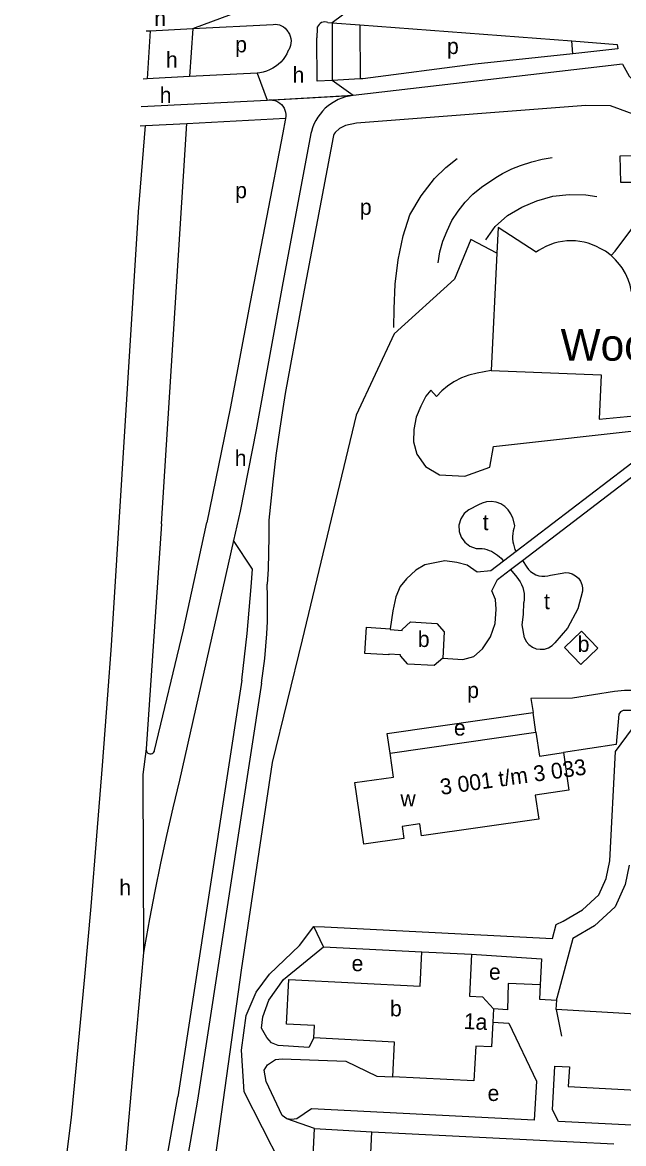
# Model space of a CAD drawing. Extents: x 161773 to 163836, y 384796 to 386521.
# Drawn here: x 161829.4 to 161981.1, y 385102.4 to 385385.3 of the extents above; entities that cross this region are included whole.
import ezdxf

# ---------------------------------------------------------------- set-up
doc = ezdxf.new("R2010")
doc.units = 0
for name, color, linetype in [('BLT_Basislijn', 7, 'Continuous'), ('BLT_Bebouwing', 7, 'Continuous'), ('BLT_Bebouwing_beschrifting', 7, 'Continuous'), ('BLT_Centroide', 7, 'Continuous'), ('BLT_Huisnummer', 7, 'Continuous'), ('BLT_Huisnummer_reeks', 7, 'Continuous'), ('BLT_Vlakafsluiter', 7, 'Continuous')]:
    doc.layers.add(name, color=color, linetype=linetype)

msp = doc.modelspace()

# ---------------------------------------------------------------- linework, layer by layer
at = {"layer": 'BLT_Basislijn'}
for p, q in [((161861.61, 385383.24), (161872.38, 385383.79)), ((161872.38, 385383.79), (161871.51, 385371.65)), ((161872.38, 385383.79), (161892.67, 385384.82)), ((161903.73, 385383.9), (161903.66, 385381.41)), ((161906.48, 385385.3), (161907.55, 385385.22)), ((161907.55, 385385.22), (161907.55, 385370.71)), ((161907.55, 385385.22), (161914.56, 385384.69)), ((161914.56, 385384.69), (161914.63, 385371.07)), ((161860.62, 385383.19), (161861.61, 385383.24)), ((161861.61, 385383.24), (161860.87, 385371.1)), ((161968.27, 385377.44), (161968.05, 385380.64)), ((161979.51, 385379.77), (161979.65, 385378.66)), ((161888.63, 385372.54), (161871.51, 385371.65)), ((161975.8, 385374.19), (161912.89, 385366.87)), ((161980.8, 385374.77), (161975.8, 385374.19)), ((161860.87, 385371.1), (161859.83, 385371.04)), ((161871.51, 385371.65), (161860.87, 385371.1)), ((161914.63, 385371.07), (161907.55, 385370.71)), ((161859.38, 385364.1), (161891.12, 385365.7)), ((161971.57, 385364.37), (161913.7, 385359.92)), ((161870.84, 385359.86), (161895.81, 385361.17)), ((161858.63, 385337.56), (161860.4, 385359.32)), ((161859.06, 385359.24), (161860.4, 385359.32)), ((161860.4, 385359.32), (161870.84, 385359.86)), ((161864.48, 385258.81), (161870.84, 385359.86)), ((161895.68, 385360.64), (161895.07, 385357.44)), ((161895.07, 385357.44), (161886.84, 385314.74)), ((161902.2, 385357.34), (161894.91, 385318.73)), ((161907.79, 385356.41), (161900.5, 385317.8)), ((161851.84, 385228.1), (161858.63, 385337.56)), ((161895.12, 385287.9), (161894.38, 385282.93)), ((161884.31, 385262.02), (161882.64, 385254.61)), ((161944.45, 385263.58), (161942.07, 385262.37)), ((161953.06, 385260.39), (161953.57, 385258.28)), ((161864.48, 385258.81), (161860.59, 385202.02)), ((161882.64, 385254.61), (161869, 385194.13)), ((161887.42, 385247.34), (161882.64, 385254.61)), ((161953.67, 385252.37), (161954.02, 385251.85)), ((161950.21, 385250.11), (161950.8, 385249.39)), ((161955.56, 385249.56), (161956.7, 385247.87)), ((161952.57, 385247.27), (161954.14, 385245.37)), ((161962.62, 385245.85), (161965.64, 385246.4)), ((161970.77, 385241.85), (161969.54, 385237.33)), ((161955.8, 385235.92), (161955.92, 385238.97)), ((161969.54, 385237.33), (161966.98, 385232.47)), ((161955.48, 385233.36), (161955.8, 385235.92)), ((161956.06, 385230.04), (161955.48, 385233.36)), ((161966.98, 385232.47), (161963.77, 385228.79)), ((161884.74, 385219.35), (161868.6, 385114.18)), ((161889.68, 385218.59), (161873.54, 385113.42)), ((161958.98, 385206.27), (161958.27, 385211.22)), ((161905.36, 385152.08), (161902.89, 385157.22)), ((161905.36, 385152.08), (161930.21, 385150.85)), ((161859.89, 385150.65), (161857.58, 385124.36)), ((161964.1, 385136.25), (161964.24, 385138.65)), ((161964.24, 385138.65), (161964.27, 385139.11)), ((161964.1, 385136.25), (161965.45, 385129.52)), ((161873.54, 385113.42), (161848.95, 384970.34)), ((161903.08, 385106.19), (161896.1, 385108.63)), ((161903.08, 385106.19), (161917.59, 385105.41))]:
    msp.add_line(p, q, dxfattribs=at)
for points in [[(161892.67, 385384.82), (161893.21, 385384.86), (161893.76, 385384.81), (161894.29, 385384.69), (161894.79, 385384.49), (161895.26, 385384.22), (161895.69, 385383.88), (161896.06, 385383.49), (161896.37, 385383.04), (161896.46, 385382.87)], [(161906.48, 385385.3), (161906.09, 385385.41), (161905.68, 385385.45), (161905.28, 385385.4), (161904.89, 385385.27), (161904.54, 385385.08), (161904.23, 385384.81), (161903.98, 385384.49), (161903.8, 385384.13), (161903.73, 385383.9)], [(161914.56, 385384.69), (161968.05, 385380.64)], [(161896.46, 385382.87), (161896.75, 385382.36), (161896.96, 385381.82), (161897.1, 385381.25), (161897.16, 385380.67), (161897.13, 385380.09), (161897.03, 385379.51), (161896.85, 385378.96), (161896.6, 385378.43), (161896.46, 385378.21)], [(161907.55, 385370.71), (161903.75, 385370.52), (161903.66, 385381.41)], [(161896.46, 385378.21), (161896.09, 385377.43), (161895.65, 385376.69), (161895.14, 385375.99), (161894.57, 385375.34), (161893.94, 385374.75), (161893.26, 385374.22), (161892.54, 385373.75), (161891.77, 385373.36), (161890.97, 385373.03), (161890.14, 385372.79), (161889.3, 385372.62), (161888.63, 385372.54)], [(161968.05, 385380.64), (161979.51, 385379.77)], [(161979.65, 385378.66), (161968.27, 385377.44)], [(161968.27, 385377.44), (161943.61, 385374.79), (161915.32, 385371.1), (161914.63, 385371.07)], [(161980.8, 385374.77), (161982.52, 385371.79), (161984.92, 385369.15), (161987.89, 385367.09), (161991.2, 385365.76), (161994.59, 385365.19), (161998.03, 385365.37), (162001.47, 385366.31), (162004.66, 385368.02), (162007.35, 385370.37), (162009.39, 385373.14)], [(161912.32, 385366.79), (161911.91, 385366.73), (161910.95, 385366.51), (161910.01, 385366.21), (161909.09, 385365.84), (161908.21, 385365.4), (161907.36, 385364.88), (161906.56, 385364.3), (161905.81, 385363.66), (161905.12, 385362.96), (161904.48, 385362.2), (161903.9, 385361.4), (161903.4, 385360.55), (161902.96, 385359.66), (161902.6, 385358.74), (161902.31, 385357.79), (161902.2, 385357.34)], [(161912.89, 385366.87), (161912.32, 385366.79)], [(161891.12, 385365.7), (161891.67, 385365.78), (161892.23, 385365.77), (161892.51, 385365.73)], [(161892.51, 385365.73), (161892.75, 385365.7)], [(161892.75, 385365.7), (161892.79, 385365.69), (161893.33, 385365.53), (161893.84, 385365.29), (161894.31, 385364.99), (161894.73, 385364.62), (161895.1, 385364.19), (161895.4, 385363.72), (161895.63, 385363.21), (161895.78, 385362.67), (161895.86, 385362.11), (161895.86, 385361.55), (161895.81, 385361.17)], [(162016.9, 385359.59), (162013.18, 385360.83), (162006.47, 385360.83), (161998.06, 385359.53), (161988.57, 385360.3), (161977.78, 385364.28), (161971.57, 385364.37)], [(161895.81, 385361.17), (161895.78, 385361), (161895.68, 385360.64)], [(161913.7, 385359.92), (161910.91, 385359.33), (161909.37, 385358.52), (161908.27, 385357.55), (161908.03, 385357.18), (161907.87, 385356.77), (161907.79, 385356.41)], [(161923.15, 385308.35), (161923.22, 385313.09), (161923.46, 385319.28), (161924.22, 385325.43), (161925.47, 385331.5), (161927.15, 385336.79), (161930.02, 385341.55), (161933.39, 385345.96), (161936.26, 385348.68), (161939.12, 385351.03)], [(161934.3, 385324.63), (161934.72, 385327.44), (161935.48, 385330.17), (161936.59, 385332.78), (161937.79, 385335.35), (161939.33, 385337.73), (161941.11, 385339.94), (161943.08, 385341.98), (161945.28, 385343.77), (161947.05, 385344.99), (161949.28, 385346.44), (161950.58, 385347.18), (161952.93, 385348.35), (161955.09, 385349.24), (161957.91, 385350.19), (161960.54, 385350.84), (161963.08, 385351.28)], [(161977.93, 385326.48), (161978.99, 385327.63), (161982.97, 385332.91), (161984.29, 385334.93), (161984.67, 385336.09), (161984.76, 385337.27), (161985, 385339.88), (161985.51, 385342.13), (161986.57, 385344.92), (161980.39, 385344.97), (161980.27, 385351.7), (161993.54, 385351.93), (161993.59, 385349.34), (162056.8, 385350.57)], [(161946.32, 385330.44), (161948.66, 385333.86), (161951.83, 385336.57), (161955.39, 385338.74), (161959.23, 385340.35), (161963.24, 385341.47), (161967.39, 385341.91), (161971.55, 385341.84), (161974.36, 385341.42)], [(161949.14, 385327.14), (161942.55, 385330.53), (161938.43, 385320.55), (161923.2, 385306.75), (161913.58, 385286.21), (161900, 385229.51), (161892.42, 385198.57), (161884.59, 385146.22), (161864.49, 385001.44)], [(161894.91, 385318.73), (161888.4, 385282.54), (161884.31, 385262.02)], [(161900.5, 385317.8), (161895.69, 385291.68), (161895.12, 385287.9)], [(161886.84, 385314.74), (161881.79, 385287.89), (161875.95, 385259.11)], [(161947.71, 385297.47), (161944.11, 385296.86), (161942.08, 385296.31), (161940.2, 385295.63), (161938.28, 385294.61), (161936.65, 385293.57), (161935.21, 385292.37), (161933.92, 385290.94), (161932.42, 385292.55), (161931.22, 385290.98), (161929.89, 385288.52), (161928.74, 385285.68), (161928.15, 385282.64), (161928.1, 385279.52), (161928.91, 385276.37), (161931.07, 385273.27), (161934.62, 385271.18), (161941.04, 385270.85), (161947.37, 385273.09), (161948.31, 385278.29), (161988.32, 385282.74)], [(161894.38, 385282.93), (161893.35, 385276.03), (161892.58, 385269.41), (161891.6, 385259.69)], [(161986.38, 385276.59), (161954.02, 385251.85)], [(161955.56, 385249.56), (161988.48, 385274.72), (161990.14, 385273.9), (161992.17, 385273.83), (161994.24, 385274.37), (161996.15, 385274.27)], [(161942.07, 385262.37), (161940.88, 385261.39), (161939.99, 385260.03), (161939.55, 385258.45), (161939.6, 385256.86), (161940.09, 385255.43), (161941.01, 385254.14), (161942.33, 385253.15), (161943.86, 385252.62), (161945.4, 385252.56)], [(161953.06, 385260.39), (161952.64, 385261.36), (161952.01, 385262.31), (161951.15, 385263.15), (161950.1, 385263.82), (161948.93, 385264.26), (161947.69, 385264.44), (161946.5, 385264.35), (161945.4, 385264.05), (161944.45, 385263.58)], [(161862.73, 385201.63), (161870.02, 385232.07), (161873.23, 385246.66), (161875.95, 385259.11)], [(161891.6, 385259.69), (161891.6, 385255.58), (161891.52, 385251.47), (161891.36, 385247.37), (161891.14, 385243.61)], [(161953.57, 385258.28), (161953.37, 385257.65), (161953.23, 385257), (161953.13, 385256.33), (161953.09, 385255.65), (161953.1, 385254.98), (161953.17, 385254.3), (161953.29, 385253.64), (161953.46, 385252.99), (161953.67, 385252.37)], [(161945.4, 385252.56), (161945.99, 385252.46), (161946.58, 385252.31), (161947.17, 385252.11), (161947.73, 385251.87), (161948.28, 385251.59), (161948.81, 385251.27), (161949.31, 385250.91), (161949.78, 385250.52), (161950.21, 385250.11)], [(161954.02, 385251.85), (161950.8, 385249.39)], [(161950.8, 385249.39), (161947.6, 385246.95), (161944.16, 385246.57), (161941.65, 385248.36), (161939.01, 385249.08), (161935.96, 385249.43), (161930.96, 385248.42), (161928.68, 385247.1), (161926.29, 385244.97), (161924.69, 385243.01), (161923.6, 385240.38), (161922.83, 385236.84), (161922.2, 385232.34)], [(161952.57, 385247.27), (161955.56, 385249.56)], [(161956.7, 385247.87), (161957.12, 385247.3), (161957.64, 385246.77), (161958.25, 385246.32), (161958.94, 385245.96), (161959.68, 385245.71), (161960.44, 385245.57), (161961.2, 385245.56), (161961.94, 385245.66), (161962.62, 385245.85)], [(161884.74, 385219.35), (161885.45, 385225.24), (161886.09, 385231.13), (161886.64, 385237.03), (161887.12, 385242.94), (161887.42, 385247.34)], [(161935.44, 385224.91), (161940.49, 385224.61), (161943.3, 385225.35), (161945.53, 385227.23), (161947.48, 385230.31), (161948.67, 385233.62), (161948.95, 385237.25), (161948.74, 385239.68), (161947.86, 385241.87), (161949.24, 385244.72), (161952.57, 385247.27)], [(161954.14, 385245.37), (161954.61, 385244.79), (161955.02, 385244.15), (161955.37, 385243.47), (161955.65, 385242.75), (161955.86, 385242), (161955.99, 385241.23), (161956.04, 385240.47), (161956.02, 385239.71), (161955.92, 385238.97)], [(161965.64, 385246.4), (161966.43, 385246.49), (161967.28, 385246.43), (161968.15, 385246.17), (161968.98, 385245.72), (161969.69, 385245.09), (161970.24, 385244.32), (161970.6, 385243.49), (161970.76, 385242.65), (161970.77, 385241.85)], [(161889.68, 385218.59), (161890.14, 385221.69), (161890.52, 385224.81), (161890.83, 385227.93), (161891.05, 385231.05), (161891.19, 385234.18), (161891.26, 385237.32), (161891.24, 385240.45), (161891.14, 385243.61)], [(161841.72, 385108.98), (161843.46, 385126.74), (161845.12, 385144.51), (161846.69, 385162.28), (161848.19, 385180.06), (161849.61, 385197.85), (161850.95, 385215.64), (161851.84, 385228.1)], [(161956.06, 385230.04), (161956.53, 385229.13), (161957.22, 385228.32), (161958.09, 385227.7), (161959.06, 385227.3), (161960.06, 385227.14), (161961.11, 385227.21), (161962.13, 385227.53), (161963.04, 385228.08), (161963.77, 385228.79)], [(161989.36, 385216.03), (161983.74, 385216.71), (161981.36, 385216.74), (161978.85, 385216.52), (161968.2, 385214.84), (161957.73, 385214.77), (161958.27, 385211.22)], [(161922.16, 385200.98), (161921.45, 385205.93), (161958.27, 385211.22)], [(161963.13, 385154.21), (161964.07, 385157.72), (161965.89, 385158.53), (161970.72, 385161.37), (161974.84, 385165.18), (161976.74, 385169.34), (161977.59, 385173.79), (161979.06, 385201.33), (161986.47, 385211.34)], [(161986.47, 385211.34), (161983.4, 385211.71), (161981.8, 385211.74), (161980.96, 385211.7), (161980.32, 385211.39), (161979.89, 385210.76), (161979.2, 385203.14), (161965.93, 385201.07)], [(161860.59, 385202.02), (161860.58, 385201.72), (161860.65, 385201.44), (161860.79, 385201.18), (161860.99, 385200.97), (161861.25, 385200.82), (161861.53, 385200.74), (161861.83, 385200.75), (161862.11, 385200.83), (161862.36, 385200.99), (161862.56, 385201.2), (161862.69, 385201.47), (161862.73, 385201.63)], [(161869, 385194.13), (161867.33, 385187.16), (161865.73, 385180.17), (161864.22, 385173.17), (161862.78, 385166.15), (161861.42, 385159.12), (161860.14, 385152.07), (161859.89, 385150.65)], [(161982.47, 385172.71), (161981.54, 385167.8), (161978.96, 385162.19), (161973.72, 385157.34), (161968.29, 385154.14), (161964.27, 385139.11)], [(161894.55, 385097.32), (161885.32, 385115.47), (161884.66, 385125.98), (161885.84, 385134.74), (161888.36, 385140.63), (161891.73, 385145.18), (161899.3, 385152.42), (161902.89, 385157.22)], [(161902.89, 385157.22), (161905.61, 385157.08), (161963.13, 385154.21)], [(161902.88, 385129.08), (161901.66, 385126.65), (161893.91, 385127.16), (161892.23, 385127.83), (161891.05, 385129.18), (161889.71, 385131.54), (161890.04, 385134.4), (161891.56, 385138.61), (161895.26, 385143.83), (161905.36, 385152.08)], [(161942.73, 385150.22), (161960.4, 385149.05), (161960.05, 385142.45)], [(161960.05, 385142.45), (161951.97, 385142.86), (161951.8, 385136.16), (161948.23, 385136.42)], [(161960.05, 385142.45), (161959.91, 385138.9), (161964.24, 385138.65)], [(162003.19, 385134), (162000, 385134.18), (161964.1, 385136.25)], [(161948.06, 385133.03), (161952.17, 385132.81), (161959.09, 385118.2), (161958.54, 385108.36), (161902.37, 385111.19), (161898.63, 385108.63), (161897.28, 385108.46), (161896.1, 385108.63)], [(161857.58, 385124.36), (161855.16, 385096.84), (161852.87, 385075.31), (161848.12, 385043.24), (161835.82, 384961.76)], [(161896.1, 385108.63), (161894.92, 385109.47), (161890.89, 385118.06), (161890.38, 385120.92), (161891.22, 385122.27), (161893.24, 385123.62), (161894.92, 385123.79), (161910.96, 385123.18), (161918.83, 385119.45), (161922.82, 385119.26)], [(161996.86, 385115.27), (161999.89, 385106.23), (161964.68, 385108), (161963.14, 385110.94), (161963.76, 385121.93), (161967.41, 385121.79), (161967.15, 385116.81), (161996.86, 385115.27)], [(161841.4, 384953.23), (161842.72, 384968.87), (161868.6, 385114.18)], [(161829.37, 385015.04), (161831.79, 385032.09), (161834.13, 385049.14), (161836.4, 385066.2), (161838.58, 385083.28), (161840.69, 385100.36), (161841.72, 385108.98)], [(161923.17, 385068.89), (161901.33, 385069.99), (161903.08, 385106.19)]]:
    msp.add_lwpolyline(points, dxfattribs=at)
at = {"layer": 'BLT_Bebouwing'}
for p, q in [((161922.16, 385200.98), (161958.98, 385206.27)), ((161930.21, 385150.85), (161942.73, 385150.22)), ((161948.23, 385136.42), (161948.06, 385133.03))]:
    msp.add_line(p, q, dxfattribs=at)
for points in [[(161959.02, 385327.35), (161949.45, 385333.57), (161949.14, 385327.14)], [(161975.22, 385328.32), (161974.24, 385328.82), (161973.23, 385329.24), (161972.19, 385329.6), (161971.13, 385329.87), (161970.06, 385330.07), (161968.97, 385330.19), (161967.87, 385330.23), (161966.77, 385330.19), (161965.69, 385330.07), (161964.61, 385329.87), (161963.55, 385329.6), (161962.51, 385329.24), (161961.5, 385328.81), (161960.53, 385328.31), (161959.59, 385327.74), (161959.02, 385327.35)], [(161949.14, 385327.14), (161947.71, 385297.47)], [(161977.93, 385326.48), (161976.52, 385327.59), (161975.22, 385328.32)], [(161980.04, 385324.27), (161979.09, 385325.44), (161977.93, 385326.48)], [(161983.12, 385317.36), (161982.77, 385319.01), (161982.3, 385320.45), (161981.56, 385322), (161980.71, 385323.43), (161980.04, 385324.27)], [(161947.71, 385297.47), (161975.48, 385296.41), (161974.95, 385285.18), (161990.81, 385286.76), (161991.24, 385295.66), (161997.17, 385295.37)], [(161922.2, 385232.34), (161922.18, 385232.11), (161925.18, 385231.93), (161925.19, 385232.17), (161927.31, 385234.05), (161933.95, 385233.66), (161935.83, 385231.55), (161935.44, 385224.91)], [(161935.44, 385224.91), (161933.32, 385223.03), (161926.68, 385223.42), (161924.8, 385225.53), (161924.82, 385225.77), (161921.82, 385225.94), (161921.81, 385225.71), (161915.82, 385226.06), (161916.21, 385232.7), (161922.2, 385232.34)], [(161958.98, 385206.27), (161959.86, 385200.2), (161965.93, 385201.07)], [(161965.93, 385201.07), (161967.3, 385191.59), (161958.81, 385190.38), (161959.67, 385184.29), (161930.13, 385180.05), (161929.69, 385183.09), (161925.18, 385182.43), (161925.62, 385179.4), (161915.53, 385177.96), (161913.28, 385193.51), (161923.04, 385194.91), (161922.16, 385200.98)], [(161902.88, 385129.08), (161903.05, 385132.18), (161896.04, 385132.58), (161896.63, 385143.83), (161929.77, 385142.16), (161930.21, 385150.85)], [(161942.73, 385150.22), (161942.2, 385139.61), (161945.51, 385139.43), (161948.23, 385136.42)], [(161948.06, 385133.03), (161947.74, 385126.85), (161943.83, 385126.99), (161943.34, 385118.24), (161922.82, 385119.26)], [(161922.82, 385119.26), (161923.31, 385127.99), (161902.88, 385129.08)], [(161935.54, 385076.52), (161936.08, 385086.96), (161926.03, 385087.46), (161926.44, 385090.58), (161916.87, 385091), (161917.59, 385105.41)], [(161917.59, 385105.41), (161978.65, 385102.34)]]:
    msp.add_lwpolyline(points, dxfattribs=at)
msp.add_lwpolyline([(161966.23, 385227.58), (161970.51, 385231.7), (161974.61, 385227.44), (161970.33, 385223.32)], close=True, dxfattribs=at)
at = {"layer": 'BLT_Vlakafsluiter'}
for p, q in [((161872.38, 385383.79), (161894.22, 385391.93)), ((161915.75, 385391.36), (161907.55, 385385.22)), ((161888.63, 385372.54), (161891.12, 385365.7)), ((161912.89, 385366.87), (161907.55, 385370.71)), ((161912.89, 385366.87), (161892.51, 385365.73)), ((161912.32, 385366.79), (161892.75, 385365.7))]:
    msp.add_line(p, q, dxfattribs=at)
msp.add_lwpolyline([(161860.59, 385202.02), (161859.79, 385195.55), (161859.89, 385150.65)], dxfattribs=at)

# ---------------------------------------------------------------- texts
at = {"layer": 'BLT_Bebouwing_beschrifting'}
msp.add_text('Woonzorgcentrum', height=8, dxfattribs=at).set_placement((161965.21, 385299.97))
at = {"layer": 'BLT_Centroide'}
for s, p in [('h', (161862.64, 385384.43)), ('p', (161883.07, 385377.78)), ('h', (161865.59, 385373.93)), ('p', (161936.53, 385377.35)), ('h', (161897.54, 385370.09)), ('h', (161864.02, 385365)), ('p', (161883.07, 385340.97)), ('p', (161914.54, 385336.77)), ('h', (161882.96, 385273.42)), ('t', (161945.54, 385257.21)), ('t', (161961.01, 385237.27)), ('b', (161929.16, 385227.73)), ('b', (161969.52, 385226.5)), ('p', (161941.63, 385214.85)), ('e', (161938.28, 385205.37)), ('w', (161924.77, 385187.51)), ('h', (161853.82, 385165.03)), ('e', (161912.45, 385145.92)), ('e', (161947.12, 385143.78)), ('b', (161922.14, 385134.53)), ('e', (161946.77, 385113.17))]:
    msp.add_text(s, height=4, dxfattribs=at).set_placement(p)
at = {"layer": 'BLT_Huisnummer'}
msp.add_text('1a', height=4, rotation=356.9678, dxfattribs=at).set_placement((161940.69, 385131.38))
at = {"layer": 'BLT_Huisnummer_reeks'}
msp.add_text('3 001 t/m 3 033', height=4, rotation=8.0064, dxfattribs=at).set_placement((161935.07, 385190.4))

doc.saveas('drawing.dxf')
